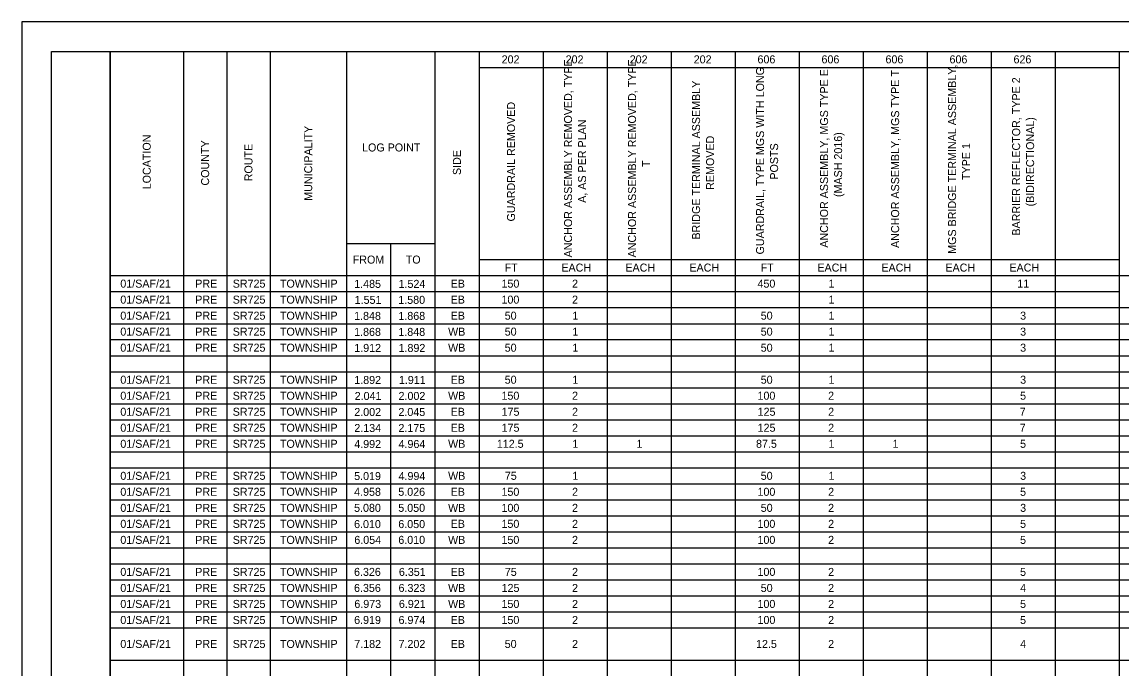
# Model space of a CAD drawing. Extents: x 0 to 34, y 0 to 22.
# Drawn here: x 0 to 18.72, y 11.01 to 22 of the extents above; entities that cross this region are included whole.
import ezdxf

# ---------------------------------------------------------------- set-up
doc = ezdxf.new("R2010")
doc.units = 0
for name, color, linetype in [('SH_Border', 7, 'Continuous'), ('SH_Cut_Line', 7, 'Continuous'), ('SH_Text', 7, 'Continuous')]:
    doc.layers.add(name, color=color, linetype=linetype)

msp = doc.modelspace()

# ---------------------------------------------------------------- linework, layer by layer
at = {"layer": 'SH_Border'}
for points in [[(0.5, 21.5), (1.5, 21.5), (1.5, 0.5), (0.5, 0.5)], [(1.5, 21.5), (33.5, 21.5), (33.5, 0.5), (1.5, 0.5)]]:
    msp.add_lwpolyline(points, close=True, dxfattribs=at)
at = {"layer": 'SH_Cut_Line'}
msp.add_lwpolyline([(0, 0), (34, 0), (34, 22), (0, 22)], close=True, dxfattribs=at)
at = {"layer": 'SH_Text'}
for p, q in [((1.5, 21.5), (27.485, 21.5)), ((1.5, 21.5), (1.5, 0.5)), ((2.75, 21.5), (2.75, 0.773)), ((3.488, 21.5), (3.488, 0.773)), ((4.225, 21.5), (4.225, 0.773)), ((5.524, 21.5), (5.524, 0.773)), ((7.031, 21.5), (7.031, 0.773)), ((7.784, 21.5), (7.784, 0.5)), ((8.874, 21.5), (8.874, 0.5)), ((9.964, 21.5), (9.964, 0.5)), ((11.054, 21.5), (11.054, 0.5)), ((12.144, 21.5), (12.144, 0.5)), ((13.234, 21.5), (13.234, 0.5)), ((14.324, 21.5), (14.324, 0.5)), ((15.415, 21.5), (15.415, 0.5)), ((16.505, 21.5), (16.505, 0.5)), ((17.595, 21.5), (17.595, 0.5)), ((18.685, 21.5), (18.685, 0.5)), ((7.784, 21.227), (18.685, 21.227)), ((5.524, 18.23), (7.031, 18.23)), ((6.277, 18.23), (6.277, 0.773)), ((7.784, 17.957), (18.685, 17.957)), ((1.5, 17.685), (27.485, 17.685)), ((1.5, 17.412), (18.685, 17.412)), ((1.5, 17.14), (27.485, 17.14)), ((1.5, 16.867), (27.485, 16.867)), ((1.5, 16.595), (27.485, 16.595)), ((1.5, 16.322), (27.485, 16.322)), ((1.5, 16.05), (27.485, 16.05)), ((1.5, 15.777), (27.485, 15.777)), ((1.5, 15.505), (27.485, 15.505)), ((1.5, 15.232), (27.485, 15.232)), ((1.5, 14.96), (27.485, 14.96)), ((1.5, 14.687), (27.485, 14.687)), ((1.5, 14.415), (27.485, 14.415)), ((1.5, 14.142), (27.485, 14.142)), ((1.5, 13.869), (27.485, 13.869)), ((1.5, 13.597), (27.485, 13.597)), ((1.5, 13.324), (27.485, 13.324)), ((1.5, 13.052), (27.485, 13.052)), ((1.5, 12.779), (27.485, 12.779)), ((1.5, 12.507), (27.485, 12.507)), ((1.5, 12.234), (27.485, 12.234)), ((1.5, 11.962), (27.485, 11.962)), ((1.5, 11.689), (27.485, 11.689)), ((1.5, 11.144), (27.485, 11.144))]:
    msp.add_line(p, q, dxfattribs=at)

# ---------------------------------------------------------------- texts
for s, height, p in [('202', 0.1363, (8.169, 21.296)), ('202', 0.1363, (9.259, 21.296)), ('202', 0.1363, (10.35, 21.296)), ('202', 0.1363, (11.44, 21.296)), ('606', 0.1363, (12.526, 21.296)), ('606', 0.1363, (13.616, 21.296)), ('606', 0.1363, (14.706, 21.296)), ('606', 0.1363, (15.796, 21.296)), ('626', 0.1363, (16.886, 21.296)), ('LOG POINT', 0.1363, (5.792, 19.797)), ('FROM', 0.1363, (5.633, 17.889)), ('TO', 0.1363, (6.536, 17.889)), ('FT', 0.1363, (8.22, 17.753)), ('EACH', 0.1363, (9.186, 17.753)), ('EACH', 0.1363, (10.276, 17.753)), ('EACH', 0.1363, (11.366, 17.753)), ('FT', 0.1363, (12.58, 17.753)), ('EACH', 0.1363, (13.546, 17.753)), ('EACH', 0.1363, (14.636, 17.753)), ('EACH', 0.1363, (15.726, 17.753)), ('EACH', 0.1363, (16.816, 17.753)), ('01/SAF/21', 0.1363, (1.675, 17.48)), ('PRE', 0.1363, (2.951, 17.48)), ('SR725', 0.1363, (3.589, 17.48)), ('TOWNSHIP', 0.1363, (4.393, 17.48)), ('1.485', 0.1363, (5.658, 17.476)), ('1.524', 0.1363, (6.413, 17.476)), ('EB', 0.1363, (7.3, 17.48)), ('150', 0.1363, (8.166, 17.48)), ('2', 0.136, (9.368, 17.48)), ('450', 0.1363, (12.526, 17.48)), ('1', 0.136, (13.735, 17.48)), ('11', 0.1363, (16.951, 17.48)), ('01/SAF/21', 0.1363, (1.675, 17.208)), ('PRE', 0.1363, (2.951, 17.208)), ('SR725', 0.1363, (3.589, 17.208)), ('TOWNSHIP', 0.1363, (4.393, 17.208)), ('1.551', 0.1363, (5.666, 17.204)), ('1.580', 0.1363, (6.409, 17.204)), ('EB', 0.1363, (7.3, 17.208)), ('100', 0.1363, (8.166, 17.208)), ('2', 0.136, (9.368, 17.208)), ('1', 0.136, (13.735, 17.208)), ('01/SAF/21', 0.1363, (1.675, 16.935)), ('PRE', 0.1363, (2.951, 16.935)), ('SR725', 0.1363, (3.589, 16.935)), ('TOWNSHIP', 0.1363, (4.393, 16.935)), ('1.848', 0.1363, (5.657, 16.931)), ('1.868', 0.1363, (6.41, 16.931)), ('EB', 0.1363, (7.3, 16.935)), ('50', 0.1363, (8.221, 16.935)), ('1', 0.136, (9.374, 16.935)), ('50', 0.1363, (12.581, 16.935)), ('1', 0.136, (13.735, 16.935)), ('3', 0.136, (16.999, 16.935)), ('01/SAF/21', 0.1363, (1.675, 16.663)), ('PRE', 0.1363, (2.951, 16.663)), ('SR725', 0.1363, (3.589, 16.663)), ('TOWNSHIP', 0.1363, (4.393, 16.663)), ('1.868', 0.1363, (5.657, 16.659)), ('1.848', 0.1363, (6.41, 16.659)), ('WB', 0.1363, (7.257, 16.663)), ('50', 0.1363, (8.221, 16.663)), ('1', 0.136, (9.374, 16.663)), ('50', 0.1363, (12.581, 16.663)), ('1', 0.136, (13.735, 16.663)), ('3', 0.136, (16.999, 16.663)), ('01/SAF/21', 0.1363, (1.675, 16.39)), ('PRE', 0.1363, (2.951, 16.39)), ('SR725', 0.1363, (3.589, 16.39)), ('TOWNSHIP', 0.1363, (4.393, 16.39)), ('1.912', 0.1363, (5.659, 16.386)), ('1.892', 0.1363, (6.413, 16.386)), ('WB', 0.1363, (7.257, 16.39)), ('50', 0.1363, (8.221, 16.39)), ('1', 0.136, (9.374, 16.39)), ('50', 0.1363, (12.581, 16.39)), ('1', 0.136, (13.735, 16.39)), ('3', 0.136, (16.999, 16.39)), ('01/SAF/21', 0.1363, (1.675, 15.845)), ('PRE', 0.1363, (2.951, 15.845)), ('SR725', 0.1363, (3.589, 15.845)), ('TOWNSHIP', 0.1363, (4.393, 15.845)), ('1.892', 0.1363, (5.659, 15.841)), ('1.911', 0.1363, (6.419, 15.841)), ('EB', 0.1363, (7.3, 15.845)), ('50', 0.1363, (8.221, 15.845)), ('1', 0.136, (9.374, 15.845)), ('50', 0.1363, (12.581, 15.845)), ('1', 0.136, (13.735, 15.845)), ('3', 0.136, (16.999, 15.845)), ('01/SAF/21', 0.1363, (1.675, 15.573)), ('PRE', 0.1363, (2.951, 15.573)), ('SR725', 0.1363, (3.589, 15.573)), ('TOWNSHIP', 0.1363, (4.393, 15.573)), ('2.041', 0.1363, (5.666, 15.569)), ('2.002', 0.1363, (6.413, 15.569)), ('WB', 0.1363, (7.257, 15.573)), ('150', 0.1363, (8.166, 15.573)), ('2', 0.136, (9.368, 15.573)), ('100', 0.1363, (12.526, 15.573)), ('2', 0.136, (13.729, 15.573)), ('5', 0.136, (16.998, 15.573)), ('01/SAF/21', 0.1363, (1.675, 15.3)), ('PRE', 0.1363, (2.951, 15.3)), ('SR725', 0.1363, (3.589, 15.3)), ('TOWNSHIP', 0.1363, (4.393, 15.3)), ('2.002', 0.1363, (5.659, 15.296)), ('2.045', 0.1363, (6.411, 15.296)), ('EB', 0.1363, (7.3, 15.3)), ('175', 0.1363, (8.168, 15.3)), ('2', 0.136, (9.368, 15.3)), ('125', 0.1363, (12.528, 15.3)), ('2', 0.136, (13.729, 15.3)), ('7', 0.136, (16.992, 15.3)), ('01/SAF/21', 0.1363, (1.675, 15.028)), ('PRE', 0.1363, (2.951, 15.028)), ('SR725', 0.1363, (3.589, 15.028)), ('TOWNSHIP', 0.1363, (4.393, 15.028)), ('2.134', 0.1363, (5.66, 15.024)), ('2.175', 0.1363, (6.411, 15.024)), ('EB', 0.1363, (7.3, 15.028)), ('175', 0.1363, (8.168, 15.028)), ('2', 0.136, (9.368, 15.028)), ('125', 0.1363, (12.528, 15.028)), ('2', 0.136, (13.729, 15.028)), ('7', 0.136, (16.992, 15.028)), ('01/SAF/21', 0.1363, (1.675, 14.755)), ('PRE', 0.1363, (2.951, 14.755)), ('SR725', 0.1363, (3.589, 14.755)), ('TOWNSHIP', 0.1363, (4.393, 14.755)), ('4.992', 0.1363, (5.659, 14.751)), ('4.964', 0.1363, (6.413, 14.751)), ('WB', 0.1363, (7.257, 14.755)), ('112.5', 0.1363, (8.087, 14.755)), ('1', 0.136, (9.374, 14.755)), ('1', 0.136, (10.465, 14.755)), ('87.5', 0.1363, (12.501, 14.755)), ('1', 0.136, (13.735, 14.755)), ('1', 0.136, (14.825, 14.755)), ('5', 0.136, (16.998, 14.755)), ('01/SAF/21', 0.1363, (1.675, 14.21)), ('PRE', 0.1363, (2.951, 14.21)), ('SR725', 0.1363, (3.589, 14.21)), ('TOWNSHIP', 0.1363, (4.393, 14.21)), ('5.019', 0.1363, (5.657, 14.206)), ('4.994', 0.1363, (6.413, 14.206)), ('WB', 0.1363, (7.257, 14.21)), ('75', 0.1363, (8.223, 14.21)), ('1', 0.136, (9.374, 14.21)), ('50', 0.1363, (12.581, 14.21)), ('1', 0.136, (13.735, 14.21)), ('3', 0.136, (16.999, 14.21)), ('01/SAF/21', 0.1363, (1.675, 13.938)), ('PRE', 0.1363, (2.951, 13.938)), ('SR725', 0.1363, (3.589, 13.938)), ('TOWNSHIP', 0.1363, (4.393, 13.938)), ('4.958', 0.1363, (5.657, 13.938)), ('5.026', 0.1363, (6.409, 13.938)), ('EB', 0.1363, (7.3, 13.938)), ('150', 0.1363, (8.166, 13.938)), ('2', 0.136, (9.368, 13.938)), ('100', 0.1363, (12.526, 13.938)), ('2', 0.136, (13.729, 13.938)), ('5', 0.136, (16.998, 13.938)), ('01/SAF/21', 0.1363, (1.675, 13.665)), ('PRE', 0.1363, (2.951, 13.665)), ('SR725', 0.1363, (3.589, 13.665)), ('TOWNSHIP', 0.1363, (4.393, 13.665)), ('5.080', 0.1363, (5.656, 13.665)), ('5.050', 0.1363, (6.409, 13.665)), ('WB', 0.1363, (7.257, 13.665)), ('100', 0.1363, (8.166, 13.665)), ('2', 0.136, (9.368, 13.665)), ('50', 0.1363, (12.581, 13.665)), ('2', 0.136, (13.729, 13.665)), ('3', 0.136, (16.999, 13.665)), ('01/SAF/21', 0.1363, (1.675, 13.393)), ('PRE', 0.1363, (2.951, 13.393)), ('SR725', 0.1363, (3.589, 13.393)), ('TOWNSHIP', 0.1363, (4.393, 13.393)), ('6.010', 0.1363, (5.656, 13.389)), ('6.050', 0.1363, (6.409, 13.389)), ('EB', 0.1363, (7.3, 13.393)), ('150', 0.1363, (8.166, 13.393)), ('2', 0.136, (9.368, 13.393)), ('100', 0.1363, (12.526, 13.393)), ('2', 0.136, (13.729, 13.393)), ('5', 0.136, (16.998, 13.393)), ('01/SAF/21', 0.1363, (1.675, 13.12)), ('PRE', 0.1363, (2.951, 13.12)), ('SR725', 0.1363, (3.589, 13.12)), ('TOWNSHIP', 0.1363, (4.393, 13.12)), ('6.054', 0.1363, (5.66, 13.12)), ('6.010', 0.1363, (6.409, 13.12)), ('WB', 0.1363, (7.257, 13.12)), ('150', 0.1363, (8.166, 13.12)), ('2', 0.136, (9.368, 13.12)), ('100', 0.1363, (12.526, 13.12)), ('2', 0.136, (13.729, 13.12)), ('5', 0.136, (16.998, 13.12)), ('01/SAF/21', 0.1363, (1.675, 12.575)), ('PRE', 0.1363, (2.951, 12.575)), ('SR725', 0.1363, (3.589, 12.575)), ('TOWNSHIP', 0.1363, (4.393, 12.575)), ('6.326', 0.1363, (5.655, 12.575)), ('6.351', 0.1363, (6.419, 12.575)), ('EB', 0.1363, (7.3, 12.575)), ('75', 0.1363, (8.223, 12.575)), ('2', 0.136, (9.368, 12.575)), ('100', 0.1363, (12.526, 12.575)), ('2', 0.136, (13.729, 12.575)), ('5', 0.136, (16.998, 12.575)), ('01/SAF/21', 0.1363, (1.675, 12.302)), ('PRE', 0.1363, (2.951, 12.302)), ('SR725', 0.1363, (3.589, 12.302)), ('TOWNSHIP', 0.1363, (4.393, 12.302)), ('6.356', 0.1363, (5.655, 12.302)), ('6.323', 0.1363, (6.413, 12.302)), ('WB', 0.1363, (7.257, 12.302)), ('125', 0.1363, (8.168, 12.302)), ('2', 0.136, (9.368, 12.302)), ('50', 0.1363, (12.581, 12.302)), ('2', 0.136, (13.729, 12.302)), ('4', 0.136, (16.999, 12.302)), ('01/SAF/21', 0.1363, (1.675, 12.03)), ('PRE', 0.1363, (2.951, 12.03)), ('SR725', 0.1363, (3.589, 12.03)), ('TOWNSHIP', 0.1363, (4.393, 12.03)), ('6.973', 0.1363, (5.66, 12.03)), ('6.921', 0.1363, (6.419, 12.03)), ('WB', 0.1363, (7.257, 12.03)), ('150', 0.1363, (8.166, 12.03)), ('2', 0.136, (9.368, 12.03)), ('100', 0.1363, (12.526, 12.03)), ('2', 0.136, (13.729, 12.03)), ('5', 0.136, (16.998, 12.03)), ('01/SAF/21', 0.1363, (1.675, 11.757)), ('PRE', 0.1363, (2.951, 11.757)), ('SR725', 0.1363, (3.589, 11.757)), ('TOWNSHIP', 0.1363, (4.393, 11.757)), ('6.919', 0.1363, (5.657, 11.757)), ('6.974', 0.1363, (6.413, 11.757)), ('EB', 0.1363, (7.3, 11.757)), ('150', 0.1363, (8.166, 11.757)), ('2', 0.136, (9.368, 11.757)), ('100', 0.1363, (12.526, 11.757)), ('2', 0.136, (13.729, 11.757)), ('5', 0.136, (16.998, 11.757)), ('01/SAF/21', 0.1363, (1.675, 11.349)), ('PRE', 0.1363, (2.951, 11.349)), ('SR725', 0.1363, (3.589, 11.349)), ('TOWNSHIP', 0.1363, (4.393, 11.349)), ('7.182', 0.1363, (5.659, 11.349)), ('7.202', 0.1363, (6.413, 11.349)), ('EB', 0.1363, (7.3, 11.349)), ('50', 0.1363, (8.221, 11.349)), ('2', 0.136, (9.368, 11.349)), ('12.5', 0.1363, (12.501, 11.349)), ('2', 0.136, (13.729, 11.349)), ('4', 0.136, (16.999, 11.349))]:
    msp.add_text(s, height=height, dxfattribs=at).set_placement(p)
for s, height, p in [('ANCHOR ASSEMBLY REMOVED, TYPE ', 0.13626, (9.368, 17.994)), ('ANCHOR ASSEMBLY REMOVED, TYPE ', 0.13626, (10.458, 17.994)), ('GUARDRAIL, TYPE MGS WITH LONG ', 0.13626, (12.638, 18.045)), ('ANCHOR ASSEMBLY, MGS TYPE E ', 0.13626, (13.728, 18.16)), ('ANCHOR ASSEMBLY, MGS TYPE T', 0.13626, (14.938, 18.155)), ('MGS BRIDGE TERMINAL ASSEMBLY, ', 0.13626, (15.908, 18.056)), ('BRIDGE TERMINAL ASSEMBLY ', 0.13626, (11.548, 18.298)), ('BARRIER REFLECTOR, TYPE 2 ', 0.13626, (16.999, 18.365)), ('GUARDRAIL REMOVED', 0.13626, (8.397, 18.606)), ('MUNICIPALITY', 0.13626, (4.943, 18.958)), ('A, AS PER PLAN', 0.13626, (9.606, 18.923)), ('(BIDIRECTIONAL)', 0.13626, (17.237, 18.862)), ('LOCATION', 0.1363, (2.193, 19.153)), ('REMOVED', 0.1363, (11.787, 19.144)), ('(MASH 2016)', 0.13626, (13.967, 19.021)), ('COUNTY', 0.1363, (3.187, 19.217)), ('ROUTE', 0.1363, (3.925, 19.289)), ('POSTS', 0.1363, (12.877, 19.318)), ('TYPE 1', 0.1363, (16.147, 19.311)), ('SIDE', 0.1363, (7.475, 19.396)), ('T', 0.136, (10.697, 19.533))]:
    msp.add_text(s, height=height, rotation=90, dxfattribs=at).set_placement(p)

doc.saveas('drawing.dxf')
